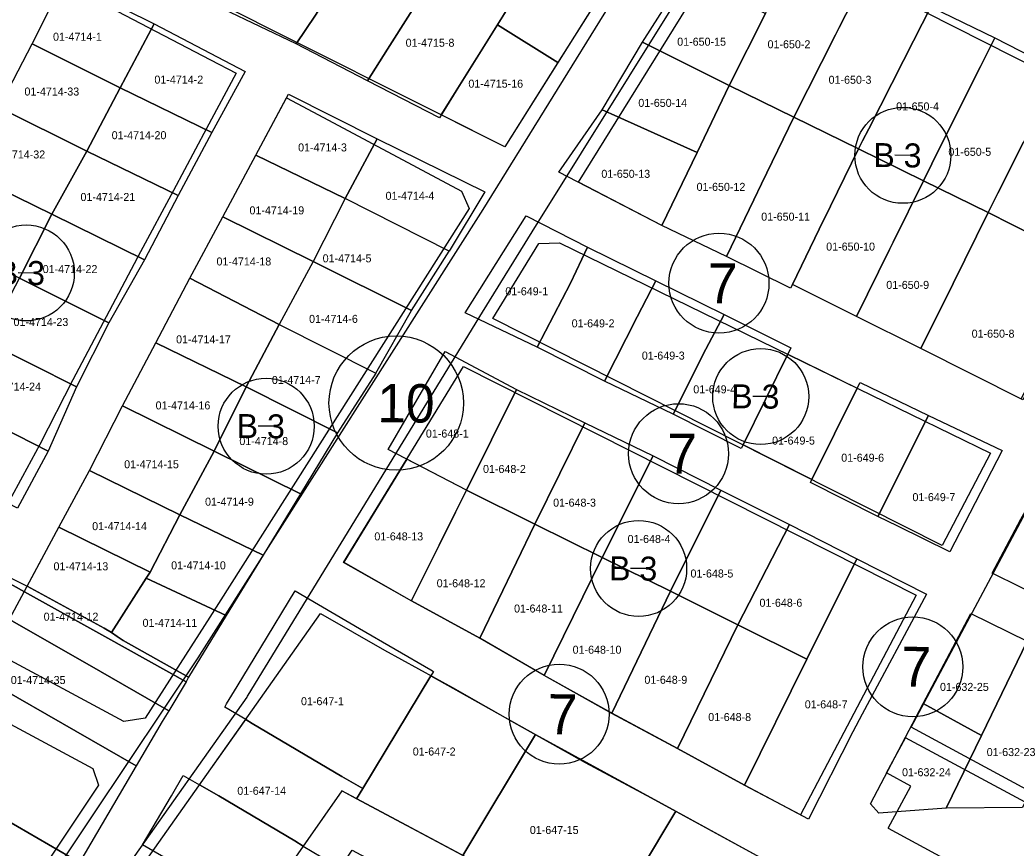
# Model space of a CAD drawing. Extents: x 413946 to 415528, y 4453939 to 4454944.
# Drawn here: x 415302.5 to 415427, y 4454061.3 to 4454164.9 of the extents above; entities that cross this region are included whole.
import ezdxf

# ---------------------------------------------------------------- set-up
doc = ezdxf.new("R2010")
doc.units = 0
for name, color, linetype in [('0_KADASTRO', 7, 'Continuous'), ('Level 27', 7, 'Continuous'), ('Level 28', 7, 'Continuous'), ('Level 29', 7, 'Continuous'), ('Level 32', 7, 'Continuous'), ('Level 58', 7, 'Continuous'), ('Level 62', 7, 'Continuous')]:
    doc.layers.add(name, color=color, linetype=linetype)

msp = doc.modelspace()

# ---------------------------------------------------------------- linework, layer by layer
at = {"layer": '0_KADASTRO'}
for p, q in [((415343.11, 4454142.56), (415339.09, 4454134.68)), ((415356.08, 4454135.96), (415343.11, 4454142.56)), ((415351.4, 4454128.56), (415356.08, 4454135.96)), ((415339.09, 4454134.68), (415334.85, 4454126.81)), ((415339.09, 4454134.68), (415351.4, 4454128.56)), ((415351.4, 4454128.56), (415339.09, 4454134.68)), ((415346.94, 4454120.71), (415351.4, 4454128.56)), ((415334.85, 4454126.81), (415346.94, 4454120.71)), ((415350.81, 4454109.97), (415342.92, 4454097.08)), ((415358.27, 4454106.08), (415350.81, 4454109.97)), ((415350.81, 4454109.97), (415350.81, 4454109.97))]:
    msp.add_line(p, q, dxfattribs=at)
for points in [[(415327.9, 4454166.25), (415330.48, 4454170.28), (415330.78, 4454170.75), (415335.7, 4454178.41), (415336.4, 4454179.51), (415337.54, 4454181.29), (415338.8, 4454183.25), (415347.77, 4454178.7), (415347.45, 4454178.19), (415345.15, 4454174.57), (415344.88, 4454174.15), (415339.38, 4454165.49), (415336.96, 4454161.9)], [(415336.96, 4454161.9), (415339.38, 4454165.49), (415344.88, 4454174.15), (415345.15, 4454174.57), (415347.45, 4454178.19), (415347.77, 4454178.7), (415356.61, 4454174.16), (415354.87, 4454171.46), (415353.77, 4454169.73), (415348.39, 4454161.21), (415345.91, 4454157.28)], [(415345.91, 4454157.28), (415348.39, 4454161.21), (415353.77, 4454169.73), (415354.87, 4454171.46), (415356.61, 4454174.16), (415365.47, 4454169.61), (415363.65, 4454166.67), (415356.98, 4454156.01), (415354.88, 4454152.66)], [(415362.15, 4454164.26), (415363.65, 4454166.67), (415365.47, 4454169.61), (415367.02, 4454172.13), (415368.93, 4454175.12), (415376.5, 4454170.38), (415369.68, 4454159.54)], [(415391.1, 4454156.67), (415395.62, 4454165.68), (415396.34, 4454167.11), (415400.13, 4454174.67), (415408.21, 4454170.57), (415404.85, 4454163.95), (415404.39, 4454163.03), (415399.16, 4454152.71)], [(415380.27, 4454162.1), (415385.62, 4454170.56), (415393.67, 4454166.63), (415394.02, 4454166.46), (415395.62, 4454165.68), (415391.1, 4454156.67), (415388.66, 4454157.89), (415381.16, 4454161.66)], [(415399.16, 4454152.71), (415404.39, 4454163.03), (415404.85, 4454163.95), (415408.21, 4454170.57), (415416.31, 4454166.51), (415414.14, 4454162.26), (415412.88, 4454159.79), (415408.53, 4454151.28), (415407.76, 4454149.78), (415407.24, 4454148.76)], [(415303.98, 4454161.91), (415308.02, 4454169.96), (415319.23, 4454164.41), (415314.97, 4454156.38)], [(415407.24, 4454148.76), (415407.76, 4454149.78), (415408.53, 4454151.28), (415412.88, 4454159.79), (415414.14, 4454162.26), (415416.31, 4454166.51), (415424.28, 4454162.63), (415422.5, 4454159.05), (415416.48, 4454147), (415416.43, 4454146.9), (415415.37, 4454144.78)], [(415314.97, 4454156.38), (415319.23, 4454164.41), (415330.59, 4454158.45), (415326.45, 4454150.8)], [(415355.09, 4454153), (415356.98, 4454156.01), (415362.15, 4454164.26), (415369.68, 4454159.54), (415363.05, 4454149)], [(415299.8, 4454153.95), (415303.98, 4454161.91), (415314.97, 4454156.38), (415310.8, 4454148.49)], [(415375.24, 4454153.64), (415380.27, 4454162.1), (415381.16, 4454161.66), (415388.66, 4454157.89), (415391.1, 4454156.67), (415387.1, 4454148.32), (415385.43, 4454149.07), (415376.34, 4454153.15)], [(415415.37, 4454144.78), (415416.43, 4454146.9), (415416.48, 4454147), (415422.5, 4454159.05), (415424.28, 4454162.63), (415432.35, 4454158.53), (415430.75, 4454155.35), (415429.42, 4454152.7), (415427.86, 4454149.6), (415424.68, 4454143.24), (415423.46, 4454140.81)], [(415382.69, 4454139.19), (415387.1, 4454148.32), (415391.1, 4454156.67), (415399.16, 4454152.71), (415395.14, 4454144.4), (415394.17, 4454142.38), (415390.75, 4454135.31)], [(415310.8, 4454148.49), (415314.97, 4454156.38), (415326.45, 4454150.8), (415322.23, 4454142.92)], [(415331.94, 4454147.99), (415336.01, 4454155.58), (415347.12, 4454150.02), (415343.11, 4454142.56)], [(415295.54, 4454145.93), (415299.8, 4454153.95), (415310.8, 4454148.49), (415306.43, 4454140.58)], [(415369.82, 4454145.85), (415375.24, 4454153.64), (415376.34, 4454153.15), (415385.43, 4454149.07), (415387.1, 4454148.32), (415382.69, 4454139.19)], [(415390.75, 4454135.31), (415394.17, 4454142.38), (415395.14, 4454144.4), (415399.16, 4454152.71), (415407.24, 4454148.76), (415403.75, 4454141.58), (415402.35, 4454138.71), (415398.99, 4454131.79), (415398.77, 4454131.36)], [(415343.11, 4454142.56), (415347.12, 4454150.02), (415360.55, 4454143.37), (415356.08, 4454135.96)], [(415423.46, 4454140.81), (415424.68, 4454143.24), (415427.86, 4454149.6), (415441.02, 4454143.15), (415436.37, 4454134.27), (415429.37, 4454137.82)], [(415306.43, 4454140.58), (415310.8, 4454148.49), (415322.23, 4454142.92), (415318.02, 4454134.9)], [(415327.81, 4454140.25), (415331.94, 4454147.99), (415343.11, 4454142.56), (415339.09, 4454134.68)], [(415398.99, 4454131.79), (415402.35, 4454138.71), (415403.75, 4454141.58), (415407.24, 4454148.76), (415415.37, 4454144.78), (415411.59, 4454137.09), (415411.13, 4454136.16), (415407.01, 4454127.79)], [(415291.29, 4454138.02), (415295.54, 4454145.93), (415306.43, 4454140.58), (415302.41, 4454132.58)], [(415407.01, 4454127.79), (415411.13, 4454136.16), (415411.59, 4454137.09), (415415.37, 4454144.78), (415423.46, 4454140.81), (415419.07, 4454131.94), (415415.03, 4454123.78)], [(415302.41, 4454132.58), (415306.43, 4454140.58), (415318.02, 4454134.9), (415313.57, 4454126.99)], [(415415.03, 4454123.78), (415419.07, 4454131.94), (415423.46, 4454140.81), (415429.37, 4454137.82), (415436.75, 4454134.07), (415427.81, 4454117.36)], [(415323.69, 4454132.6), (415327.81, 4454140.25), (415339.09, 4454134.68), (415334.85, 4454126.81)], [(415358.11, 4454128.27), (415362.87, 4454135.9), (415365.71, 4454140.37), (415373.39, 4454136.48), (415371.25, 4454131.97), (415367.09, 4454123.95)], [(415367.09, 4454123.95), (415371.25, 4454131.97), (415373.39, 4454136.48), (415381.92, 4454132.27), (415379.58, 4454127.77), (415375.5, 4454119.71)], [(415298.25, 4454124.69), (415302.41, 4454132.58), (415313.57, 4454126.99), (415309.52, 4454118.99)], [(415319.44, 4454124.51), (415323.69, 4454132.6), (415334.85, 4454126.81), (415330.71, 4454118.99)], [(415375.5, 4454119.71), (415379.58, 4454127.77), (415381.92, 4454132.27), (415390.46, 4454128.04), (415388.16, 4454123.72), (415384.09, 4454115.58)], [(415384.09, 4454115.58), (415388.16, 4454123.72), (415390.46, 4454128.04), (415398.82, 4454123.86), (415398.43, 4454123.08), (415392.83, 4454111.73), (415392.61, 4454111.28)], [(415330.71, 4454118.99), (415334.85, 4454126.81), (415346.94, 4454120.71), (415342.14, 4454113.25)], [(415294.37, 4454116.89), (415298.25, 4454124.69), (415309.52, 4454118.99), (415305.98, 4454110.95)], [(415315.29, 4454116.63), (415319.44, 4454124.51), (415330.71, 4454118.99), (415326.72, 4454110.97)], [(415348.48, 4454111.18), (415355.58, 4454123.42), (415364.52, 4454118.69), (415358.27, 4454106.08)], [(415392.83, 4454111.73), (415398.43, 4454123.08), (415407.1, 4454118.83), (415401.42, 4454107.4)], [(415401.24, 4454107.04), (415401.42, 4454107.4), (415407.1, 4454118.83), (415407.45, 4454119.54), (415416.01, 4454115.42), (415409.67, 4454102.79)], [(415326.72, 4454110.97), (415330.71, 4454118.99), (415342.14, 4454113.25), (415337.5, 4454105.63)], [(415358.27, 4454106.08), (415364.52, 4454118.69), (415373.05, 4454114.49), (415366.8, 4454101.85)], [(415290.62, 4454109.78), (415294.37, 4454116.89), (415305.98, 4454110.95), (415302.15, 4454103.83)], [(415311.13, 4454108.55), (415315.29, 4454116.63), (415326.72, 4454110.97), (415322.42, 4454103.01)], [(415366.8, 4454101.85), (415373.05, 4454114.49), (415381.59, 4454110.36), (415375.21, 4454097.68)], [(415409.67, 4454102.79), (415416.01, 4454115.42), (415425.2, 4454111.03), (415421.19, 4454103.22), (415418.66, 4454098.38), (415412.19, 4454101.6)], [(415322.42, 4454103.01), (415326.72, 4454110.97), (415337.5, 4454105.63), (415332.84, 4454097.96)], [(415375.21, 4454097.68), (415381.59, 4454110.36), (415390.05, 4454106.1), (415383.75, 4454093.44)], [(415307.3, 4454101.45), (415311.13, 4454108.55), (415322.42, 4454103.01), (415318.73, 4454095.83)], [(415423.96, 4454095.7), (415427.53, 4454102.46), (415430.84, 4454108.32), (415437.33, 4454105.02), (415431.05, 4454092.2)], [(415351.41, 4454092.24), (415358.27, 4454106.08), (415366.8, 4454101.85), (415359.94, 4454087.56)], [(415383.75, 4454093.44), (415390.05, 4454106.1), (415398.62, 4454101.79), (415392.19, 4454089.26)], [(415276.9, 4454078.11), (415279.07, 4454083.95), (415282.22, 4454092.7), (415285.89, 4454102.89), (415286.84, 4454102.36), (415297.69, 4454096.32), (415303.03, 4454093.35), (415313.42, 4454087.57), (415323.21, 4454082.12), (415321.05, 4454078.5), (415311.13, 4454084.19), (415301.43, 4454089.76), (415296.11, 4454092.81), (415295.03, 4454093.43), (415290.97, 4454086.54), (415283.89, 4454074.49), (415283.82, 4454074.38), (415277.14, 4454077.99)], [(415286.84, 4454102.36), (415288.7, 4454101.55), (415298.58, 4454096.45), (415303.35, 4454094.09), (415312.99, 4454088.83), (415313.9, 4454088.28), (415314.6, 4454087.8), (415315.34, 4454087.3), (415323.54, 4454082.68), (415323.21, 4454082.12), (415313.42, 4454087.57), (415303.03, 4454093.35), (415297.69, 4454096.32)], [(415318.23, 4454095.06), (415318.73, 4454095.83), (415322.42, 4454103.01), (415332.84, 4454097.96), (415328.23, 4454090.39)], [(415359.94, 4454087.56), (415366.8, 4454101.85), (415375.21, 4454097.68), (415367.97, 4454082.92)], [(415392.19, 4454089.26), (415398.62, 4454101.79), (415407.03, 4454097.49), (415400.82, 4454084.96)], [(415303.35, 4454094.09), (415307.3, 4454101.45), (415318.73, 4454095.83), (415318.23, 4454095.06), (415313.9, 4454088.28), (415312.99, 4454088.83)], [(415367.97, 4454082.92), (415375.21, 4454097.68), (415383.75, 4454093.44), (415376.41, 4454078.18)], [(415393.02, 4454069.2), (415400.82, 4454084.96), (415407.03, 4454097.49), (415415.75, 4454093.08), (415407.73, 4454078.06), (415406.56, 4454075.86), (415401, 4454064.96)], [(415313.9, 4454088.28), (415318.23, 4454095.06), (415328.23, 4454090.39), (415323.54, 4454082.68), (415315.34, 4454087.3), (415314.6, 4454087.8)], [(415290.97, 4454086.54), (415295.03, 4454093.43), (415296.11, 4454092.81), (415301.43, 4454089.76), (415311.13, 4454084.19), (415321.05, 4454078.5), (415320.24, 4454077.14), (415316.99, 4454071.61)], [(415328.05, 4454078.96), (415328.29, 4454079.36), (415329.6, 4454081.53), (415332.55, 4454086.39), (415336.86, 4454093.49), (415344.88, 4454088.8), (415353.79, 4454083.6), (415354.13, 4454083.4), (415353.81, 4454082.88), (415345.29, 4454068.79), (415342.67, 4454070.28), (415331.49, 4454076.92), (415330.68, 4454077.4)], [(415376.41, 4454078.18), (415383.75, 4454093.44), (415392.19, 4454089.26), (415384.63, 4454073.78)], [(415415.32, 4454079.41), (415421.28, 4454090.66), (415428.33, 4454087.2), (415422.61, 4454075.4)], [(415384.63, 4454073.78), (415392.19, 4454089.26), (415400.82, 4454084.96), (415393.02, 4454069.2)], [(415418.22, 4454066.33), (415422.61, 4454075.4), (415428.33, 4454087.2), (415436.17, 4454083.5), (415427.77, 4454066.41)], [(415283.82, 4454074.38), (415283.89, 4454074.49), (415290.97, 4454086.54), (415316.99, 4454071.61), (415309.89, 4454059.54), (415296.93, 4454067.02), (415293.94, 4454068.73), (415288.26, 4454071.99)], [(415344.51, 4454067.5), (415345.29, 4454068.79), (415353.81, 4454082.88), (415366.87, 4454075.51), (415357.81, 4454060.4)], [(415408.77, 4454066.84), (415415.32, 4454079.41), (415422.61, 4454075.4), (415418.22, 4454066.33), (415409.81, 4454065.67)], [(415324.91, 4454069.22), (415330.68, 4454077.4), (415331.49, 4454076.92), (415342.67, 4454070.28), (415345.29, 4454068.79), (415344.51, 4454067.5), (415342.68, 4454068.47), (415337.87, 4454061.57), (415336.79, 4454062.21), (415327.31, 4454067.86)], [(415357.81, 4454060.4), (415366.87, 4454075.51), (415384.42, 4454065.92), (415375.49, 4454050.97), (415366.64, 4454055.69)], [(415317.78, 4454061.74), (415321.41, 4454067.87), (415322.85, 4454070.38), (415324.91, 4454069.22), (415327.31, 4454067.86), (415336.79, 4454062.21), (415337.87, 4454061.57), (415340.11, 4454060.23), (415337.59, 4454055.82), (415335.13, 4454051.54), (415331.66, 4454053.69), (415329.01, 4454055.23), (415322.03, 4454059.29)], [(415372.41, 4454045.81), (415375.49, 4454050.97), (415366.64, 4454055.69), (415357.81, 4454060.4), (415344.51, 4454067.5), (415342.68, 4454068.47), (415337.87, 4454061.57), (415340.11, 4454060.23), (415337.59, 4454055.82), (415339.69, 4454054.63), (415343.96, 4454061.08), (415354.75, 4454055.29), (415363.57, 4454050.56)], [(415286.47, 4454049.27), (415296.85, 4454066.88), (415296.93, 4454067.02), (415309.89, 4454059.54), (415299.75, 4454042.3)], [(415375.49, 4454050.97), (415384.42, 4454065.92), (415395.84, 4454059.69), (415396.79, 4454046.53), (415384.78, 4454046.02)]]:
    msp.add_lwpolyline(points, close=True, dxfattribs=at)
msp.add_lwpolyline([(415342.92, 4454097.08), (415351.41, 4454092.24), (415355.62, 4454100.75), (415358.27, 4454106.08)], dxfattribs=at)
at = {"layer": 'Level 27'}
for p, q in [((415372.28, 4454144.58), (415392.67, 4454177.52)), ((415342.91, 4454097.05), (415357.89, 4454121.55))]:
    msp.add_line(p, q, dxfattribs=at)
for points in [[(415404.5, 4454171.52), (415445.11, 4454150.94), (415427.56, 4454117.48)], [(415255.23, 4454068.48), (415258.37, 4454074.28), (415262.69, 4454082.27), (415266.83, 4454090.32), (415270.94, 4454098.34), (415275.53, 4454107.93), (415279.41, 4454115.27), (415283.11, 4454122.3), (415287.21, 4454130.12), (415291.29, 4454138.02), (415295.54, 4454145.93), (415299.8, 4454153.95), (415303.98, 4454161.91), (415307.82, 4454169.56)], [(415427.81, 4454117.36), (415415.03, 4454123.78), (415407.01, 4454127.79), (415398.99, 4454131.79), (415398.77, 4454131.36), (415390.75, 4454135.31), (415382.69, 4454139.19), (415372.28, 4454144.58)], [(415357.64, 4454143.48), (415358.59, 4454141.29), (415326.17, 4454090.22)], [(415361.55, 4454127.54), (415367.32, 4454136.91), (415369.89, 4454137.02)], [(415369.89, 4454137.02), (415403.93, 4454120.39)], [(415403.77, 4454106.2), (415361.55, 4454127.54)], [(415357.89, 4454121.55), (415403.68, 4454098.41)], [(415403.93, 4454120.39), (415423.75, 4454110.71), (415417.72, 4454099.16)], [(415403.93, 4454120.39), (415403.93, 4454120.39)], [(415403.93, 4454120.39), (415403.93, 4454120.39)], [(415417.72, 4454099.16), (415403.77, 4454106.2)], [(415403.68, 4454098.41), (415414.46, 4454092.96), (415403.39, 4454071.89)], [(415403.68, 4454098.41), (415403.68, 4454098.41)], [(415403.68, 4454098.41), (415403.68, 4454098.41)], [(415400.02, 4454065.49), (415393.06, 4454069.17), (415384.67, 4454073.75), (415376.44, 4454078.16), (415367.99, 4454082.89), (415359.96, 4454087.52), (415351.43, 4454092.2), (415342.91, 4454097.05)], [(415340.03, 4454090.64), (415348.02, 4454086.09), (415356.53, 4454081.42), (415364.54, 4454076.81), (415373.08, 4454072.02), (415381.34, 4454067.59), (415395.84, 4454059.69)], [(415326.17, 4454090.22), (415318.12, 4454077.55)], [(415326.17, 4454090.22), (415326.17, 4454090.22)], [(415403.39, 4454071.89), (415400.02, 4454065.49)], [(415403.39, 4454071.89), (415403.39, 4454071.89)], [(415403.39, 4454071.89), (415403.39, 4454071.89)], [(415312.26, 4454069.2), (415310.17, 4454066.08)], [(415310.17, 4454066.08), (415299.44, 4454050.01)]]:
    msp.add_lwpolyline(points, dxfattribs=at)
at = {"layer": 'Level 28'}
for p, q in [((415315.42, 4454077.16), (415298.99, 4454085.99)), ((415289.52, 4454083.14), (415311.58, 4454071.28)), ((415318.12, 4454077.55), (415315.42, 4454077.16)), ((415311.58, 4454071.28), (415312.26, 4454069.2))]:
    msp.add_line(p, q, dxfattribs=at)
msp.add_lwpolyline([(415396.79, 4454046.53), (415384.78, 4454046.02), (415342.68, 4454068.47), (415328.12, 4454047.58)], dxfattribs=at)
at = {"layer": 'Level 29'}
for p, q in [((415383.57, 4454181.62), (415363.05, 4454149)), ((415363.05, 4454149), (415314.59, 4454173.37)), ((415316.86, 4454057.83), (415340.03, 4454090.64)), ((415494.15, 4454033.07), (415413.84, 4454076.44))]:
    msp.add_line(p, q, dxfattribs=at)
for points in [[(415307.82, 4454169.56), (415326.26, 4454159.9)], [(415326.26, 4454159.9), (415329.48, 4454158.22)], [(415329.48, 4454158.22), (415325.77, 4454151.29), (415321.64, 4454143.56), (415317.51, 4454135.89), (415313.24, 4454127.77), (415309.08, 4454119.86), (415304.94, 4454111.81), (415301.14, 4454104.77), (415289.52, 4454083.14)], [(415298.99, 4454085.99), (415307.3, 4454101.45), (415311.13, 4454108.55), (415315.29, 4454116.63), (415319.44, 4454124.51), (415323.69, 4454132.6), (415327.81, 4454140.25), (415331.94, 4454147.99), (415335.78, 4454155.14)], [(415335.78, 4454155.14), (415340.4, 4454152.68)], [(415340.4, 4454152.68), (415357.64, 4454143.48)], [(415413.84, 4454076.44), (415430.83, 4454108.32)]]:
    msp.add_lwpolyline(points, dxfattribs=at)
at = {"layer": 'Level 32'}
for p, q in [((415413.8, 4454147.94), (415411.8, 4454147.96)), ((415304.25, 4454133.23), (415302.25, 4454133.25)), ((415396.04, 4454117.78), (415394.04, 4454117.8)), ((415334.23, 4454114.07), (415332.23, 4454114.08)), ((415380.78, 4454096.28), (415378.78, 4454096.3))]:
    msp.add_line(p, q, dxfattribs=at)
for centre in [(415412.8, 4454147.95), (415303.25, 4454133.24), (415395.04, 4454117.79), (415333.23, 4454114.08), (415379.78, 4454096.29)]:
    msp.add_circle(centre, 6, dxfattribs=at)
at = {"layer": 'Level 58'}
for centre, radius in [((415389.82, 4454131.96), 6.25), ((415349.48, 4454116.97), 8.4), ((415384.76, 4454110.64), 6.25), ((415414.05, 4454083.99), 6.25), ((415369.85, 4454078.07), 6.25)]:
    msp.add_circle(centre, radius, dxfattribs=at)
at = {"layer": 'Level 62'}
for p, q in [((415384.84, 4454180.82), (415360.29, 4454141.16)), ((415366.46, 4454138.38), (415391.39, 4454178.31)), ((415330.98, 4454080.43), (415360.28, 4454128.33)), ((415315.64, 4454058.69), (415330.84, 4454080.21)), ((415410.76, 4454070.73), (415413.13, 4454075.12)), ((415494.15, 4454031.37), (415413.13, 4454075.12)), ((415413.79, 4454069.08), (415410.76, 4454070.73)), ((415410.95, 4454063.81), (415413.79, 4454069.08))]:
    msp.add_line(p, q, dxfattribs=at)
for points in [[(415360.29, 4454141.16), (415327.53, 4454089.56)], [(415360.28, 4454128.33), (415366.46, 4454138.38)], [(415327.53, 4454089.56), (415324.91, 4454085.44)], [(415327.53, 4454089.56), (415327.53, 4454089.56)], [(415324.86, 4454085.36), (415311.5, 4454065.37)], [(415311.5, 4454065.37), (415297.18, 4454043.93)], [(415410.95, 4454063.81), (415493.86, 4454018.82)]]:
    msp.add_lwpolyline(points, dxfattribs=at)
for centre, start, end in [((415321.53, 4454087.58), 326.2509, 327.5901), ((415327.57, 4454082.52), 324.7709, 328.5467)]:
    msp.add_arc(centre, 4, start, end, dxfattribs=at)

# ---------------------------------------------------------------- texts
at = {"layer": '0_KADASTRO'}
for s, p in [('01-4714-1', (415306.59, 4454162.28)), ('01-4715-8', (415350.66, 4454161.53)), ('01-650-15', (415384.6, 4454161.66)), ('01-650-2', (415395.89, 4454161.34)), ('01-4714-2', (415319.26, 4454156.92)), ('01-650-3', (415403.52, 4454156.9)), ('01-4715-16', (415358.5, 4454156.41)), ('01-4714-33', (415303.02, 4454155.43)), ('01-650-14', (415379.74, 4454154.01)), ('01-650-4', (415411.96, 4454153.57)), ('01-4714-20', (415313.92, 4454149.97)), ('01-4714-3', (415337.22, 4454148.44)), ('01-4714-32', (415298.77, 4454147.56)), ('01-650-5', (415418.49, 4454147.89)), ('01-650-13', (415375.12, 4454145.14)), ('01-650-12', (415387.02, 4454143.51)), ('01-4714-21', (415310.02, 4454142.24)), ('01-4714-4', (415348.15, 4454142.39)), ('01-4714-19', (415331.14, 4454140.57)), ('01-650-11', (415395.1, 4454139.78)), ('01-650-10', (415403.22, 4454136.04)), ('01-4714-5', (415340.29, 4454134.57)), ('01-4714-22', (415305.3, 4454133.23)), ('01-4714-18', (415327.02, 4454134.18)), ('01-650-9', (415410.73, 4454131.25)), ('01-649-1', (415363.12, 4454130.45)), ('01-4714-6', (415338.59, 4454127)), ('01-4714-23', (415301.66, 4454126.61)), ('01-649-2', (415371.41, 4454126.44)), ('01-4714-17', (415321.97, 4454124.44)), ('01-650-8', (415421.4, 4454125.15)), ('01-649-3', (415380.18, 4454122.41)), ('01-4714-24', (415298.24, 4454118.53)), ('01-4714-7', (415333.94, 4454119.36)), ('01-649-4', (415386.61, 4454118.19)), ('01-4714-16', (415319.41, 4454116.18)), ('01-648-1', (415353.19, 4454112.66)), ('01-4714-8', (415329.88, 4454111.72)), ('01-649-5', (415396.46, 4454111.78)), ('01-649-6', (415405.1, 4454109.64)), ('01-4714-15', (415315.48, 4454108.82)), ('01-648-2', (415360.33, 4454108.23)), ('01-649-7', (415414, 4454104.71)), ('01-4714-9', (415325.59, 4454104.14)), ('01-648-3', (415369.09, 4454104.02)), ('01-4714-14', (415311.48, 4454101.08)), ('01-648-13', (415346.75, 4454099.8)), ('01-648-4', (415378.4, 4454099.48)), ('01-4714-13', (415306.65, 4454096.06)), ('01-4714-10', (415321.35, 4454096.18)), ('01-648-5', (415386.26, 4454095.16)), ('01-648-12', (415354.54, 4454093.94)), ('01-648-6', (415394.88, 4454091.5)), ('01-4714-12', (415305.42, 4454089.76)), ('01-648-11', (415364.21, 4454090.78)), ('01-4714-11', (415317.78, 4454088.99)), ('01-648-10', (415371.53, 4454085.63)), ('01-4714-35', (415301.31, 4454081.84)), ('01-648-9', (415380.5, 4454081.87)), ('01-632-25', (415417.44, 4454080.98)), ('01-647-1', (415337.58, 4454079.19)), ('01-648-7', (415400.54, 4454078.8)), ('01-648-8', (415388.48, 4454077.21)), ('01-647-2', (415351.55, 4454072.9)), ('01-632-23', (415423.28, 4454072.83)), ('01-632-24', (415412.7, 4454070.31)), ('01-647-14', (415329.62, 4454067.99)), ('01-647-15', (415366.18, 4454063.09))]:
    msp.add_text(s, height=1, dxfattribs=at).set_placement(p)
at = {"layer": 'Level 32'}
for p in [(415409.1, 4454146.49), (415299.55, 4454131.78), (415391.34, 4454116.33), (415329.53, 4454112.61), (415376.08, 4454094.82)]:
    msp.add_text('B 3', height=3, rotation=359.4141, dxfattribs=at).set_placement(p)
at = {"layer": 'Level 58'}
for s, height, p in [('7', 5, (415388.38, 4454129.47)), ('10', 4.8, (415347.11, 4454114.59)), ('7', 5, (415412.61, 4454081.51)), ('7', 5, (415368.4, 4454075.58))]:
    msp.add_text(s, height=height, rotation=359.4141, dxfattribs=at).set_placement(p)
msp.add_text('7', height=5, dxfattribs=at).set_placement((415383.34, 4454108.14))

doc.saveas('drawing.dxf')
